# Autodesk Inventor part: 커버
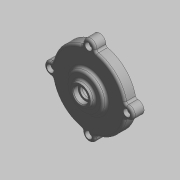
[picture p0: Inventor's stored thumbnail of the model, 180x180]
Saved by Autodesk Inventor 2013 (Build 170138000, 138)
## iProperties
Created: 2015-11
Part Number: 커버
Document SubType Name: 모델링
Designer: mdu
Material: 알루미늄 6061
Density: 1 g/cm^3
변환 표준: STEP AP214IS
파일 이름: C:\Users\SeoGD\Desktop\?쒗뿕\而ㅻ쾭-1.stp
전처리기: Build: 253, Release: 2010 SP1 - Date: Wed 07/29/2009
전송 단위: 밀리미터
불확실성: 0.01
Author: mdu
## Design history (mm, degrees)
sketch "스케치1"
  geometry: L1 (0, 0)-(0, 26); L2 (50, 0)-(50, 15); L3 (50, 15)-(25, 15); L4 (25, 15)-(25, 21); L5 (25, 21)-(15, 21); L6 (15, 21)-(13.66, 26); L7 (13.66, 26)-(10, 26); L8 (50, 0)-(45, 0); L9 (45, 0)-(45, 10); L10 (45, 10)-(14.5, 10); L11 (14.5, 10)-(13.266, 3); L12 (13.266, 3)-(11, 3); L13 (11, 3)-(11, 16); L14 (11, 16)-(7.5, 16); L15 (7.5, 16)-(7.5, 19); L16 (7.5, 19)-(10, 19); L17 (10, 19)-(10, 26)
  constraints: 34 end point, 10 parallel, 2 perpendicular, 2 point on line, 1 vertical
  dimensions: "d11" = 100 diameter of L2 L1; "d12" = 22 diameter of L13 L1; "d13" = 90 diameter of L9 L1; "d14" = 15 distance between parallel lines of L3 L8; "d15" = 10 distance between parallel lines of L8 L10; "d16" = 29 diameter of L10.end L1; "d17" = 100 deg angle of L11 L10; "d18" = 7 distance between parallel lines of L12 L10; "d19" = 13 distance between parallel lines of L14 L12; "d20" = 3 distance between parallel lines of L16 L14; "d21" = 15 diameter of L15 L1; "d22" = 20 diameter of L17 L1; "d23" = 30 diameter of L5.end L1; "d24" = 6 distance between parallel lines of L5 L3; "d25" = 50 diameter of L4 L1; "d26" = 105 deg angle of L5 L6; "d50" = 26 distance of L1.start L1.end
revolve "회전1" sketch "스케치1" stored, may be unused: angle "d27" = 90 deg
sketch "스케치2" dims "d29" = 104
  geometry: A1 r 8.5 centre (0, 52) between (8.074, 49.344) and (-8.074, 49.344); A2 r 50 centre (0, 0) between (-8.074, 49.344) and (8.074, 49.344) reference; 2 further points
  constraints: 4 point on circle, 2 vertical alignment, 1 centre point, 1 coincident, 2 other
  dimensions: "d28" = 17 diameter of A1
extrude "돌출1" join sketch "스케치2" stored distance "d30" = 10; taper "d31" = 0 deg
fillet "모깎기3" dims "d32" = 3
fillet "모깎기4" dims "d45" = 3, "d46" = 0.2
chamfer "모따기1" distance "d47" = 1; stored, may be unused: second distance "d48" = 2, angle "d49" = 45 deg
hole "구멍2" diameter "d38" = 5.5; stored, may be unused: countersink angle "d42" = 90 deg, drill point angle "d44" = 118 deg; dims "d39" = 6, "d40" = 9.5, "d41" = 5.4, "d43" = 8, "d54" = 10, "d55" = 10
node "솔리드1"
node "솔리드 본체"
node "곡면 본체"
pattern_circular "원형 패턴1" dims angle "d34" = 360 deg
pattern_circular "원형 패턴2" dims angle "d52" = 360 deg
node "솔리드2"
